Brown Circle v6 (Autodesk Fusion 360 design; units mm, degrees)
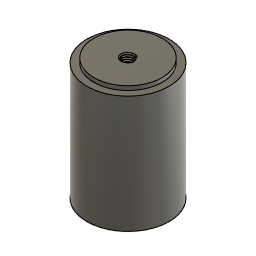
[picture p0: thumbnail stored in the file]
sketch "Sketch1" plane through (0, 0, 0) normal (0, 1, 0) x axis (1, 0, 0)
  circle C1 centre (0, 0) radius 29.75
  point P1 (0, 0)
  point P2 (0, 0)
  coincident P1 P2
  dimension "d1" diameter C1 = 59.5
extrude "Extrude1" new body sketch "Sketch1" along normal blind 85
sketch "Sketch1" plane through (0, 85, 0) normal (0, 1, 0) x axis (-1, 0, 0)
  circle C1 centre (0, 0) radius 29.75
  circle C2 centre (0, 0) radius 24.75
  point P1 (0, 0)
  point P3 (0, 0)
  coincident P1 P3
  dimension "d4" diameter C2 = 49.5
extrude "Extrude1" new body sketch "Sketch1" profile of C2 along normal blind 3
hole "Hole1" HoleDepth 22.5 HoleDiameter 8.526 TipAngle 180
hole "Hole2" HoleDepth 63 HoleDiameter 8.526 TipAngle 180
offset_faces "OffsetFaces1" distance -0.1
offset_faces "OffsetFaces2" distance -0.1
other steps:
hole "Hole1" HoleDepth 22.5 HoleDiameter 8.526 TipAngle 180
thread "Thread1"
thread "Thread1"
thread "Thread2"
create_component "CreateComponent1"
create_component "CreateComponent2"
